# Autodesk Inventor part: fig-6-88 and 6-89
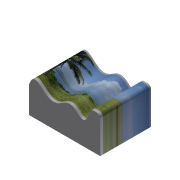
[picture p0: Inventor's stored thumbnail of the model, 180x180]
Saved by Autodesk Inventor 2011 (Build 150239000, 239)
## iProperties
Shininess: 64.0
Length Units: 11269
Angle Units: 11279
Time Units: 11290
Mass Units: 11283
Length Display Precision: 3
Angle Display Precision: 2
Compacted: True
Part Number: fig-6-88 and 6-89
Document SubType Name: Modeling
Created: 2002-12
Designer: deepak
Density: 1 g/cm^3
Density: 0.0
Volumn: 0.0
Area: 0.0
PropertySet Name: Model Information
Control State: 0
Master: False
Checked Out: False
Author: deepak
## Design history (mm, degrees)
sketch "Sketch1"
  geometry: L1 (-39.922, 26.809)-(19.509, 26.809); L2 (19.509, 26.809)-(19.509, -15.568); L3 (19.509, -15.568)-(-39.922, -15.568); L4 (-39.922, -15.568)-(-39.922, 26.809)
  constraints: 8 end point, 2 parallel, 1 horizontal, 1 perpendicular
extrude "Extrusion1" new body sketch "Sketch1" distance "d0" = 30; taper "d1" = 0 deg
sketch "Sketch2"
  geometry: L1 (59.432, 30)-(0, 30) reference; L2 (0, 0)-(0, 30) reference; L3 (0, 21.728)-(0, 30); 5 further points
  constraints: 2 end point, 2 point on line, 1 collinear, 6 other
extrude "Extrusion2" cut sketch "Sketch2" stored distance "d2" = 30; taper "d3" = 0 deg
fillet "Fillet1" dims "d4" = 3
workplane "Work Plane1"
sketch "Sketch3"
  geometry: L1 (-40.776, 25.358)-(20.879, 25.358); L2 (20.879, 25.358)-(20.879, -13.177); L3 (20.879, -13.177)-(-40.776, -13.177); L4 (-40.776, -13.177)-(-40.776, 25.358); 1 other entity
  constraints: 2 other
feature "Decal3" sketch "Sketch3"
body "Solid1"
node "Image2"
other parameters: "d6" = 35
